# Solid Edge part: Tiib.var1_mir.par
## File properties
Author: jaanm
Template: Ansi Inch Part.par
Last saved by: jaanm
Revision: 2
Application: Solid Edge
Accuracy: 0,990
Username: jaanm
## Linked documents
Tiib.var1.par
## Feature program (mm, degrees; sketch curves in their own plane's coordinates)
part copy "CopiedPart_1"
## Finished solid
Body 1: solid body, 10 faces, 15 edges, 7 vertices.
  Faces by surface: spline 5, plane 3, cylinder 2
  Edges by curve: circle 5, spline 5, curve on surface 4, line 1
Bounding box of the edges (mm; curved faces can reach further): 1533.444 x 505.897 x 269.127, from (-20, -333.359, -49.7014) to (1513.4443, 172.5379, 219.4251).
Cylindrical faces by radius (mm): R5 x2
Planar faces by outward normal: -x 3
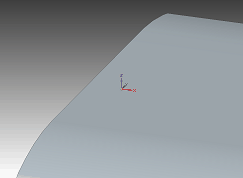
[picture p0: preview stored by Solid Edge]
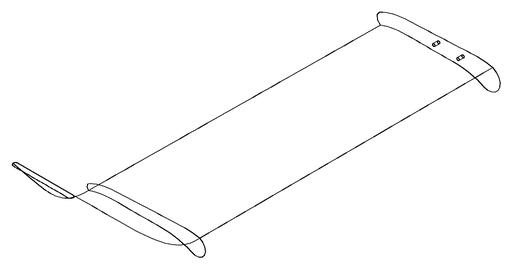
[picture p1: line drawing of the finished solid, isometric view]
